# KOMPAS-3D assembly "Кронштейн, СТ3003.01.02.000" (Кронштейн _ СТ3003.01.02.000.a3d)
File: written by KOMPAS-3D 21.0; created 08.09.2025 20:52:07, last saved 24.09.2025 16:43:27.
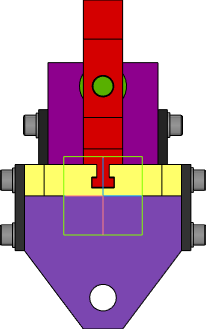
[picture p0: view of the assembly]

Document properties: Полное имя файла: C:\Users\1\Yandex.Disk\Документы\Новая папка\Стапель №2\Стапель _ СТ3003.00.00.000\Опора _ СТ3003.01.00.000\3D\Кронштейн _ СТ3003.01.02.000\Кронштейн _ СТ3003.01.02.000.a3d

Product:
- Part/product: Кронштейн  | designation СТ3003.01.02.000
    Масса: 4.787723
    Форматы листов документа: A3
  - Component [standard]: Винт М8-6gx25.56.019 ГОСТ 11738-84  | qty 10  | pos. 8  | Материал: Сталь 30 ГОСТ 1050-2013 (density 1000 kg/m3); Масса: 0.01513; Раздел спецификации: Стандартные изделия; Рассекать на разрезах: no
  - Component [standard]: Шайба A.8.01.10.019 ГОСТ 11371-78  | qty 10  | pos. 10  | Масса: 0.001828; Раздел спецификации: Стандартные изделия; Рассекать на разрезах: no
  - Component [detail]: Винт  | designation СТ3003.01.01.001  | pos. 1  | Материал: Круг$d30 ГОСТ 2590-2006;Ст3сп ГОСТ 535-2005$ (density 7850 kg/m3); Масса: 0.311599; Форматы листов документа: A4; additional columns: 110; source file: ..\..\2D\Кронштейн _ СТ3003.01.01.000\Винт _ СТ3003.01.01.001.cdw, ..\Кронштейн _ СТ3003.01.01.000\Винт _ СТ3003.01.01.001.m3d
  - Component [detail]: Упор  | designation СТ3003.01.02.003  | pos. 6  | Материал: Сталь 45  ГОСТ 1050-2013 (density 7810 kg/m3); Масса: 0.784266; Форматы листов документа: A3; source file: Упор _ СТ3003.01.02.003.m3d
  - Component [detail]: Косынка  | designation СТ3003.01.01.002  | qty 4  | pos. 2  | Материал: Лист$dБ-ПН-НО-6 ГОСТ 19903-2015;Ст3сп ГОСТ 14637-89$ (density 7850 kg/m3); Масса: 0.116828; Форматы листов документа: A4; source file: ..\Кронштейн _ СТ3003.01.01.000\Косынка _ СТ3003.01.01.002.m3d
  - Component [detail]: Пластина  | designation СТ3003.01.01.006  | pos. 3  | Материал: Лист$dБ-ПН-НО-16 ГОСТ 19903-2015;Ст3сп ГОСТ 14637-89$ (density 7850 kg/m3); Масса: 0.669577; Форматы листов документа: A4; source file: ..\Кронштейн _ СТ3003.01.01.000\Пластина _ СТ3003.01.01.006.m3d
  - Component [detail]: Направляющая  | designation СТ3003.01.02.001  | pos. 4  | Материал: Сталь 45  ГОСТ 1050-2013 (density 7810 kg/m3); Масса: 1.56864; Форматы листов документа: A3; source file: ..\..\2D\Кронштейн _ СТ3003.01.02.000\Направляющая _ СТ3003.01.02.001.cdw, Направляющая _ СТ3003.01.02.001.m3d
  - Component [detail]: Пластина  | designation СТ3003.01.02.002  | pos. 5  | Материал: Лист$dБ-ПН-НО-16 ГОСТ 19903-2015;Ст3сп ГОСТ 14637-89$ (density 7850 kg/m3); Масса: 0.780129; Форматы листов документа: A3; source file: Пластина _ СТ3003.01.02.002.m3d
  - Component [standard]: Винт М8-6gx35.56.019 ГОСТ 11738-84  | qty 2  | pos. 9  | Материал: Сталь 30 ГОСТ 1050-2013 (density 1000 kg/m3); Масса: 0.01831; Раздел спецификации: Стандартные изделия; Рассекать на разрезах: no

Referenced files in C:\Users\1\Yandex.Disk\Документы\Новая папка\Стапель №2\Оправка 500\Опора _ О500.02.00.000\Кронштейн _ О500.02.02.000\: Направляющая _ О500.02.02.001.m3d, Упор _ О500.02..02.004.m3d, Пластина _ О500.02.02.003.m3d, Пластина _ О500.02.02.002.m3d
Referenced files in C:\Users\1\Yandex.Disk\Документы\Новая папка\Стапель №2\Оправка 500\Опора _ О500.02.00.000\Кронштейн _ О500.02.01.000\: Косынка _ О500.02.01.002.m3d, Винт _ О500.02.01.001.m3d
Referenced files in C:\Users\1\Yandex.Disk\Документы\Новая папка\Стапель №2\Стапель _ СТ3003.00.00.000\Опора _ СТ3003.01.00.000\3D\Кронштейн _ СТ3003.01.02.000\: Пластина _ СТ3003.01.02.002.m3d, Направляющая _ СТ3003.01.02.001.m3d, Упор _ СТ3003.01.02.003.m3d
Referenced files in C:\Users\1\Yandex.Disk\Документы\Новая папка\Стапель №2\Стапель _ СТ3003.00.00.000\Опора _ СТ3003.01.00.000\2D\Кронштейн _ СТ3003.01.02.000\: Направляющая _ СТ3003.01.02.001.cdw
Referenced files in C:\Users\1\Yandex.Disk\Документы\Новая папка\Стапель №2\Стапель _ СТ3003.00.00.000\Опора _ СТ3003.01.00.000\3D\Кронштейн _ СТ3003.01.01.000\: Пластина _ СТ3003.01.01.006.m3d, Винт _ СТ3003.01.01.001.m3d, Косынка _ СТ3003.01.01.002.m3d
Referenced files in C:\Users\1\Yandex.Disk\Документы\Новая папка\Стапель №2\Стапель _ СТ3003.00.00.000\Опора _ СТ3003.01.00.000\2D\Кронштейн _ СТ3003.01.01.000\: Винт _ СТ3003.01.01.001.cdw
Referenced files in C:\Program Files\ASCON\KOMPAS-3D v21\Libs\PartLib\DATA\VAULT\Methods\Kompas\3D\: PLib_Screw_GOST_11738_1500.m3d, PLib_Washer_1_712.m3d
Referenced files in C:\Program Files\ASCON\KOMPAS-3D v21\Libs\PARTLib\DATA\vault\Methods\Kompas\3D\: PLib_Screw_GOST_11738_1500.m3d
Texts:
  Крепежное изделие ГОСТ
  СТ3003.01.02.002
  СТ3003.01.02.001
  СТ3003.01.01.006
  СТ3003.01.02.003
  СТ3003.01.01.001
  СТ3003.01.01.002
  СТ3003.01.02.000
  СТ3003.01.02.002 Пластина
  СТ3003.01.02.001 Направляющая
  СТ3003.01.01.006 Пластина
  СТ3003.01.01.002 Косынка (1)
  СТ3003.01.01.002 Косынка (2)
  СТ3003.01.01.002 Косынка (3)
  СТ3003.01.01.002 Косынка (4)
  СТ3003.01.02.003 Упор
  СТ3003.01.01.001 Винт
  Винт М8-6gx25.56.019 ГОСТ 11738-84 (1)
  Винт М8-6gx25.56.019 ГОСТ 11738-84 (2)
  Шайба A.8.01.10.019 ГОСТ 11371-78 (1)
  Шайба A.8.01.10.019 ГОСТ 11371-78 (2)
  Шайба A.8.01.10.019 ГОСТ 11371-78 (3)
  Шайба A.8.01.10.019 ГОСТ 11371-78 (4)
  Шайба A.8.01.10.019 ГОСТ 11371-78 (5)
  Шайба A.8.01.10.019 ГОСТ 11371-78 (6)
  Шайба A.8.01.10.019 ГОСТ 11371-78 (7)
  Шайба A.8.01.10.019 ГОСТ 11371-78 (8)
  Винт М8-6gx25.56.019 ГОСТ 11738-84 (3)
  Винт М8-6gx25.56.019 ГОСТ 11738-84 (4)
  Винт М8-6gx25.56.019 ГОСТ 11738-84 (5)
  Винт М8-6gx25.56.019 ГОСТ 11738-84 (6)
  Винт М8-6gx25.56.019 ГОСТ 11738-84 (7)
  Винт М8-6gx25.56.019 ГОСТ 11738-84 (8)
  Винт М8-6gx25.56.019 ГОСТ 11738-84 (9)
  Винт М8-6gx25.56.019 ГОСТ 11738-84 (10)
  Шайба A.8.01.10.019 ГОСТ 11371-78 (9)
  Шайба A.8.01.10.019 ГОСТ 11371-78 (10)
  Винт М8-6gx35.56.019 ГОСТ 11738-84 (1)
  Винт М8-6gx35.56.019 ГОСТ 11738-84 (2)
